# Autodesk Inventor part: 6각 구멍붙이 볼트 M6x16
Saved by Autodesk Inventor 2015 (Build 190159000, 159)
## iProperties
Created: 2025-11
Part Number: 6각 구멍붙이 볼트 M6x16
Material: 일반
Document SubType Name: Modeling
Designer: user
Density: 1 g/cm^3
Appearance: 기본값
Author: user
Author: jhkim
Description: 6각머리 태핑 나사
Creation Date: 2025-10-31
Sending System: Autodesk Inventor 2026
Preprocessor: ST-DEVELOPER v20.1
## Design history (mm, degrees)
node "6각 구멍붙이 볼트 M6x161"
body "Solid1"
node "기준1"
